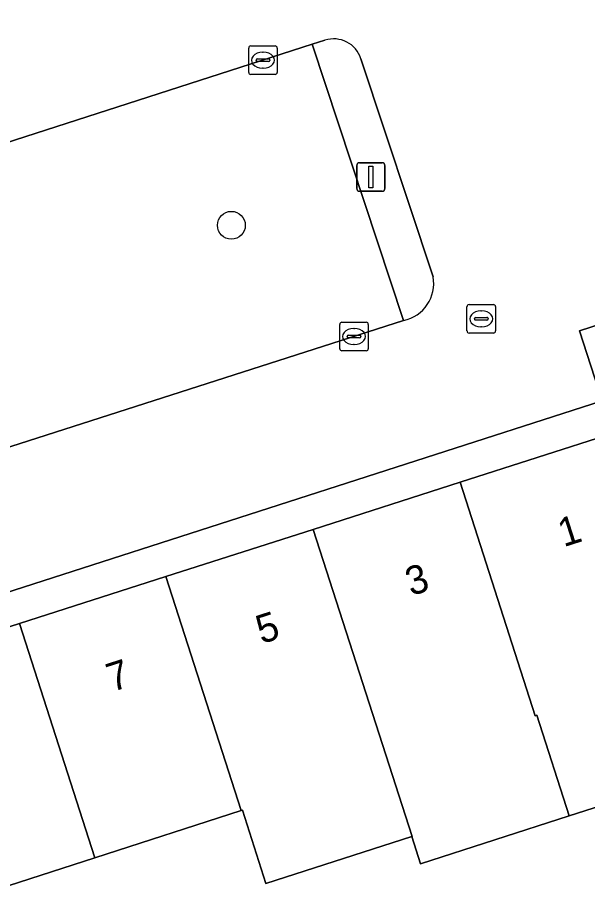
# Model space of a CAD drawing. Extents: x 159371 to 159986, y 382987 to 383597.
# Drawn here: x 159548.69 to 159568.65, y 383184.9 to 383215.85 of the extents above; entities that cross this region are included whole.
import ezdxf

# ---------------------------------------------------------------- set-up
doc = ezdxf.new("R2010")
doc.units = 0
for name, color, linetype in [('IMGEO_Boom', 7, 'Continuous'), ('IMGEO_Erf', 7, 'Continuous'), ('IMGEO_Kolk', 7, 'Continuous'), ('IMGEO_Lichtmast', 7, 'Continuous'), ('IMGEO_Pand', 7, 'Continuous'), ('IMGEO_Pand_nummerreeks', 7, 'Continuous'), ('IMGEO_Parkeervlak_open', 7, 'Continuous'), ('IMGEO_Rijbaan_lokaal_open', 7, 'Continuous'), ('IMGEO_Rioolput', 7, 'Continuous'), ('IMGEO_Voetpad_open', 7, 'Continuous')]:
    doc.layers.add(name, color=color, linetype=linetype)

msp = doc.modelspace()

# ---------------------------------------------------------------- linework, layer by layer
at = {"layer": 'IMGEO_Boom'}
msp.add_circle((159556.178, 383208.58), 0.489, dxfattribs=at)
at = {"layer": 'IMGEO_Erf'}
msp.add_lwpolyline([(159575.068, 383184.185), (159572.197, 383193.137), (159572.175, 383193.13), (159573.31, 383189.59), (159568.017, 383187.893), (159562.8, 383186.22), (159562.495, 383187.169), (159557.389, 383185.532), (159556.567, 383188.097), (159556.521, 383188.082), (159551.391, 383186.428), (159546.069, 383184.712)], dxfattribs=at)
at = {"layer": 'IMGEO_Kolk'}
for p, q in [((159556.785, 383213.938), (159556.785, 383214.79)), ((159556.86, 383214.864), (159557.712, 383214.864)), ((159557.273, 383214.644), (159557.298, 383214.644)), ((159557.786, 383214.79), (159557.786, 383213.938)), ((159557.044, 383214.358), (159557.044, 383214.37)), ((159557.482, 383214.321), (159557.084, 383214.321)), ((159557.087, 383214.407), (159557.485, 383214.407)), ((159557.528, 383214.37), (159557.528, 383214.358)), ((159557.296, 383214.084), (159557.271, 383214.084)), ((159557.712, 383213.864), (159556.86, 383213.864)), ((159559.975, 383204.259), (159559.975, 383205.111)), ((159560.05, 383205.185), (159560.902, 383205.185)), ((159560.976, 383205.111), (159560.976, 383204.259)), ((159560.277, 383204.728), (159560.675, 383204.728)), ((159560.463, 383204.965), (159560.488, 383204.965)), ((159560.234, 383204.679), (159560.234, 383204.691)), ((159560.672, 383204.642), (159560.274, 383204.642)), ((159560.718, 383204.691), (159560.718, 383204.679)), ((159560.902, 383204.185), (159560.05, 383204.185)), ((159560.486, 383204.405), (159560.461, 383204.405))]:
    msp.add_line(p, q, dxfattribs=at)
for points in [[(159556.785, 383213.938), (159556.785, 383214.79)], [(159556.86, 383214.864), (159557.712, 383214.864)], [(159557.786, 383214.79), (159557.786, 383213.938)], [(159557.712, 383213.864), (159556.86, 383213.864)], [(159559.975, 383204.259), (159559.975, 383205.111)], [(159560.05, 383205.185), (159560.902, 383205.185)], [(159560.976, 383205.111), (159560.976, 383204.259)], [(159560.902, 383204.185), (159560.05, 383204.185)]]:
    msp.add_lwpolyline(points, dxfattribs=at)
for centre, radius, start, end in [((159556.862, 383214.788), 0.0765, 91.552, 178.448), ((159556.862, 383214.788), 0.0765, 91.552, 178.448), ((159557.71, 383214.788), 0.0765, 1.552, 88.448), ((159557.71, 383214.788), 0.0765, 1.552, 88.448), ((159557.084, 383214.367), 0.0403, 85.8775, 175.7526), ((159557.081, 383214.357), 0.0366, 178.938, 274.7102), ((159557.485, 383214.364), 0.043, 264.8664, 352.4533), ((159557.489, 383214.369), 0.0386, 1.7309, 96.639), ((159556.862, 383213.94), 0.0765, 181.552, 268.448), ((159556.862, 383213.94), 0.0765, 181.552, 268.448), ((159557.71, 383213.94), 0.0765, 271.552, 358.448), ((159557.71, 383213.94), 0.0765, 271.552, 358.448), ((159560.052, 383205.109), 0.0765, 91.552, 178.448), ((159560.052, 383205.109), 0.0765, 91.552, 178.448), ((159560.9, 383205.109), 0.0765, 1.552, 88.448), ((159560.9, 383205.109), 0.0765, 1.552, 88.448), ((159560.274, 383204.688), 0.0403, 85.8775, 175.7526), ((159560.679, 383204.69), 0.0386, 1.7309, 96.639), ((159560.271, 383204.678), 0.0366, 178.938, 274.7102), ((159560.675, 383204.685), 0.043, 264.8664, 352.4533), ((159560.052, 383204.261), 0.0765, 181.552, 268.448), ((159560.052, 383204.261), 0.0765, 181.552, 268.448), ((159560.9, 383204.261), 0.0765, 271.552, 358.448), ((159560.9, 383204.261), 0.0765, 271.552, 358.448)]:
    msp.add_arc(centre, radius, start, end, dxfattribs=at)
for centre, major_axis, ratio, start_param, end_param in [((159557.272, 383214.364), (-0.387, 0.002), 0.722429, 4.712389, 7.853982), ((159557.297, 383214.364), (-0.39, 0.002), 0.717154, 1.570796, 4.712389), ((159560.462, 383204.685), (-0.387, 0.002), 0.722429, 4.712389, 7.853982), ((159560.487, 383204.685), (-0.39, 0.002), 0.717154, 1.570796, 4.712389)]:
    msp.add_ellipse(centre, major_axis=major_axis, ratio=ratio, start_param=start_param, end_param=end_param, dxfattribs=at)
at = {"layer": 'IMGEO_Lichtmast'}
for p, q in [((159560.57, 383209.871), (159560.57, 383210.671)), ((159560.57, 383210.671), (159560.57, 383209.871)), ((159560.67, 383210.771), (159561.46, 383210.771)), ((159561.46, 383210.771), (159560.67, 383210.771)), ((159561.56, 383210.671), (159561.56, 383209.871)), ((159561.56, 383209.871), (159561.56, 383210.671)), ((159561.46, 383209.771), (159560.67, 383209.771)), ((159560.67, 383209.771), (159561.46, 383209.771))]:
    msp.add_line(p, q, dxfattribs=at)
msp.add_lwpolyline([(159560.99, 383210.646), (159561.14, 383210.646), (159561.14, 383209.896), (159560.99, 383209.896), (159560.99, 383210.646)], dxfattribs=at)
for centre, start, end in [((159560.67, 383210.671), 90, 180), ((159560.67, 383210.671), 90, 180), ((159561.46, 383210.671), 0, 90), ((159561.46, 383210.671), 360, 90), ((159560.67, 383209.871), 180, 270), ((159560.67, 383209.871), 180, 270), ((159561.46, 383209.871), 270, 0), ((159561.46, 383209.871), 270, 0)]:
    msp.add_arc(centre, 0.1, start, end, dxfattribs=at)
at = {"layer": 'IMGEO_Pand'}
for points in [[(159569.587, 383201.314), (159564.189, 383199.583), (159566.818, 383191.4), (159566.885, 383191.422), (159568.017, 383187.893), (159573.31, 383189.59), (159572.175, 383193.13), (159572.197, 383193.137)], [(159564.189, 383199.583), (159559.039, 383197.931), (159562.517, 383187.176), (159562.495, 383187.169), (159562.8, 383186.22), (159568.017, 383187.893), (159566.885, 383191.422), (159566.818, 383191.4)], [(159559.039, 383197.931), (159553.888, 383196.279), (159556.521, 383188.082), (159556.567, 383188.097), (159557.389, 383185.532), (159562.495, 383187.169), (159562.517, 383187.176)], [(159553.888, 383196.279), (159548.757, 383194.633), (159551.391, 383186.428), (159556.521, 383188.082)], [(159551.391, 383186.428), (159548.757, 383194.633), (159543.404, 383192.916), (159546.069, 383184.712)]]:
    msp.add_lwpolyline(points, close=True, dxfattribs=at)
at = {"layer": 'IMGEO_Parkeervlak_open'}
msp.add_lwpolyline([(159543.744, 383199.332), (159562.21, 383205.251), (159559.015, 383214.923), (159540.707, 383209.028)], dxfattribs=at)
at = {"layer": 'IMGEO_Rijbaan_lokaal_open'}
for points in [[(159591.243, 383219.067), (159572.368, 383213.005), (159570.5, 383218.852), (159566.151, 383217.448), (159564.747, 383221.794), (159528.425, 383210.177), (159529.915, 383205.553), (159540.074, 383208.824), (159540.707, 383209.028), (159559.015, 383214.923), (159559.453, 383215.064)], [(159562.21, 383205.251), (159543.744, 383199.332), (159543.216, 383199.162), (159541.549, 383198.628), (159543.044, 383194.025), (159569.171, 383202.429), (159568.377, 383204.889), (159593.923, 383213.154), (159594.442, 383213.217), (159592.24, 383219.664)], [(159560.719, 383214.415), (159563.245, 383206.781)]]:
    msp.add_lwpolyline(points, dxfattribs=at)
for centre, radius, start, end in [((159559.759, 383214.101), 1.01, 18.0923, 107.6249), ((159561.955, 383206.539), 1.313, 281.2117, 10.6339)]:
    msp.add_arc(centre, radius, start, end, dxfattribs=at)
at = {"layer": 'IMGEO_Rioolput'}
for p, q in [((159564.433, 383204.88), (159564.433, 383205.732)), ((159564.508, 383205.806), (159565.36, 383205.806)), ((159565.434, 383205.732), (159565.434, 383204.88)), ((159564.735, 383205.349), (159565.133, 383205.349)), ((159564.921, 383205.586), (159564.946, 383205.586)), ((159564.692, 383205.3), (159564.692, 383205.312)), ((159565.13, 383205.263), (159564.732, 383205.263)), ((159565.176, 383205.312), (159565.176, 383205.3)), ((159565.36, 383204.806), (159564.508, 383204.806)), ((159564.944, 383205.026), (159564.919, 383205.026))]:
    msp.add_line(p, q, dxfattribs=at)
for points in [[(159564.433, 383204.88), (159564.433, 383205.732)], [(159564.508, 383205.806), (159565.36, 383205.806)], [(159565.434, 383205.732), (159565.434, 383204.88)], [(159565.36, 383204.806), (159564.508, 383204.806)]]:
    msp.add_lwpolyline(points, dxfattribs=at)
for centre, radius, start, end in [((159564.51, 383205.73), 0.0765, 91.552, 178.448), ((159564.51, 383205.73), 0.0765, 91.552, 178.448), ((159565.358, 383205.73), 0.0765, 1.552, 88.448), ((159565.358, 383205.73), 0.0765, 1.552, 88.448), ((159564.732, 383205.309), 0.0403, 85.8775, 175.7526), ((159565.137, 383205.311), 0.0386, 1.7309, 96.639), ((159564.729, 383205.299), 0.0366, 178.938, 274.7102), ((159565.133, 383205.306), 0.043, 264.8664, 352.4533), ((159564.51, 383204.882), 0.0765, 181.552, 268.448), ((159564.51, 383204.882), 0.0765, 181.552, 268.448), ((159565.358, 383204.882), 0.0765, 271.552, 358.448), ((159565.358, 383204.882), 0.0765, 271.552, 358.448)]:
    msp.add_arc(centre, radius, start, end, dxfattribs=at)
for centre, major_axis, ratio, start_param, end_param in [((159564.92, 383205.306), (-0.387, 0.002), 0.722429, 4.712389, 7.853982), ((159564.945, 383205.306), (-0.39, 0.002), 0.717154, 1.570796, 4.712389)]:
    msp.add_ellipse(centre, major_axis=major_axis, ratio=ratio, start_param=start_param, end_param=end_param, dxfattribs=at)
at = {"layer": 'IMGEO_Voetpad_open'}
for points in [[(159559.453, 383215.064), (159559.015, 383214.923), (159562.21, 383205.251)], [(159563.245, 383206.781), (159560.719, 383214.415)]]:
    msp.add_lwpolyline(points, dxfattribs=at)
msp.add_lwpolyline([(159595.914, 383209.856), (159594.442, 383213.217), (159593.923, 383213.154), (159568.377, 383204.889), (159569.171, 383202.429), (159543.044, 383194.025), (159541.465, 383193.517), (159541.825, 383192.407), (159543.404, 383192.916), (159548.757, 383194.633), (159553.888, 383196.279), (159559.039, 383197.931), (159564.189, 383199.583), (159569.587, 383201.314), (159570.855, 383201.726), (159587.539, 383207.143)], close=True, dxfattribs=at)
for centre, radius, start, end in [((159559.759, 383214.101), 1.01, 18.0923, 107.6249), ((159561.955, 383206.539), 1.313, 281.2117, 10.6339)]:
    msp.add_arc(centre, radius, start, end, dxfattribs=at)

# ---------------------------------------------------------------- texts
at = {"layer": 'IMGEO_Pand_nummerreeks'}
for s, rotation, p in [('1', 17.7846, (159567.816, 383197.302)), ('3', 17.7846, (159562.472, 383195.587)), ('5', 17.7846, (159557.235, 383193.908)), ('7', 17.7833, (159551.999, 383192.228))]:
    msp.add_text(s, height=1, rotation=rotation, dxfattribs=at).set_placement(p)

doc.saveas('drawing.dxf')
